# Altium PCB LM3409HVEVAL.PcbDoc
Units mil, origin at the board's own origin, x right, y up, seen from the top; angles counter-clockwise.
Board outline 6000 x 4000 mil, 2 copper layers (Top Layer, Bottom Layer); 38 components, 19 nets, 100 pads, 4 vias.
Unrouted connection lines stored in the file: 78.
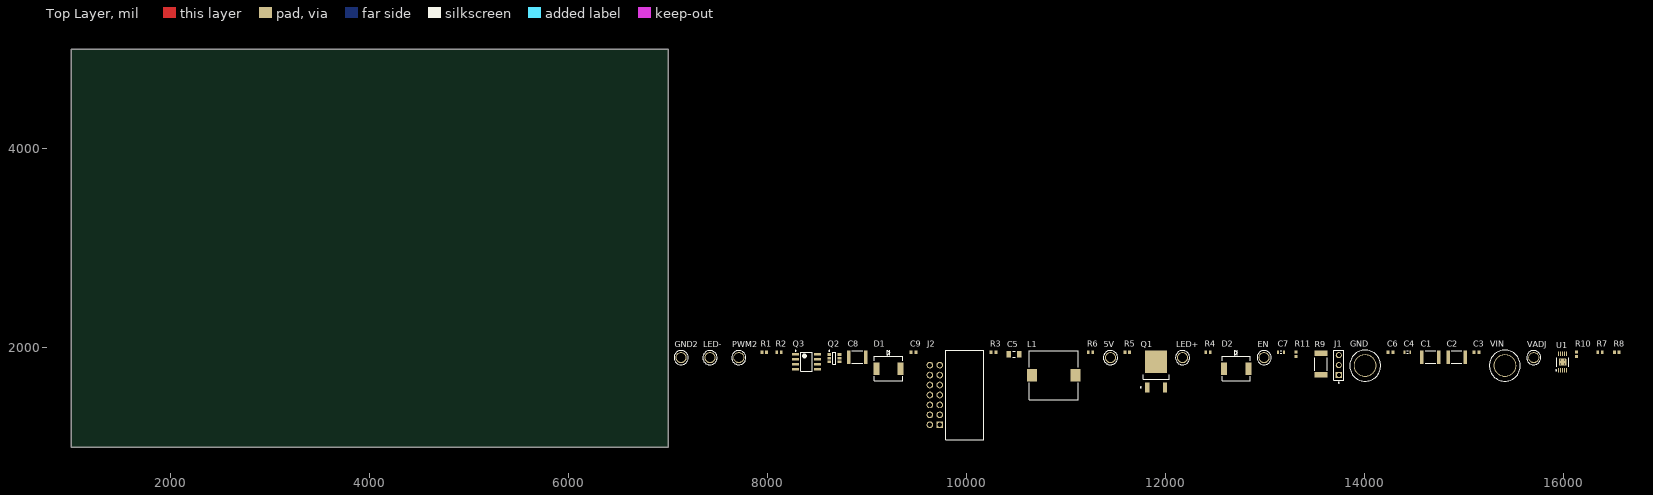
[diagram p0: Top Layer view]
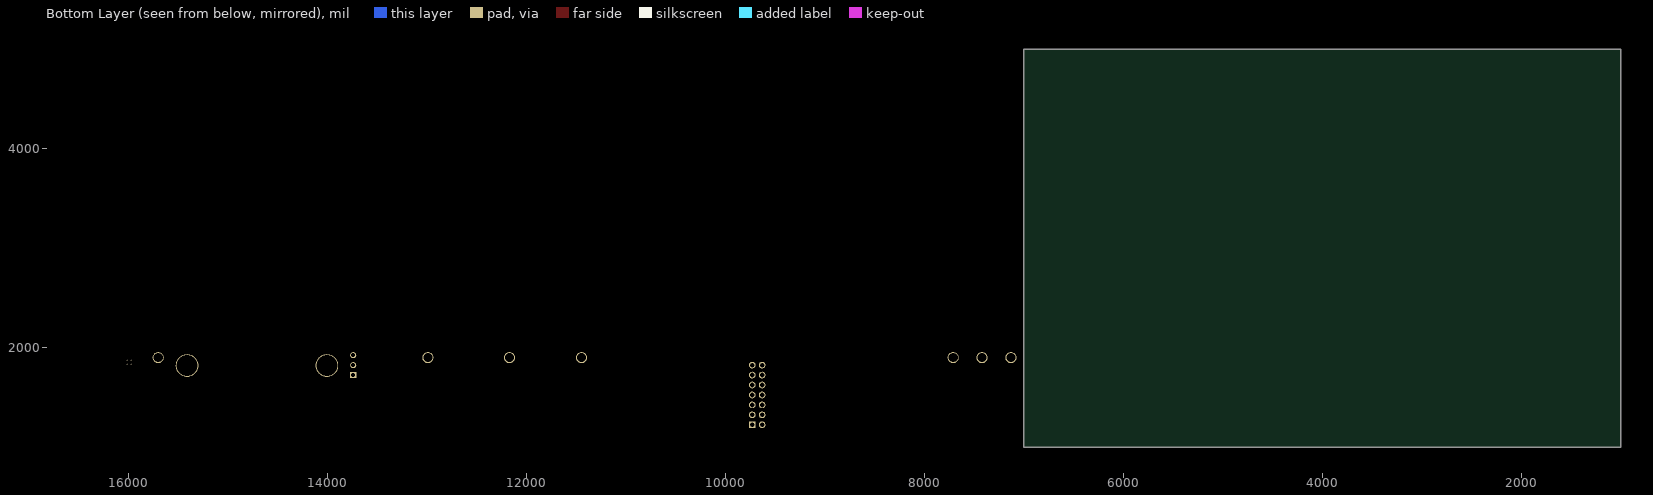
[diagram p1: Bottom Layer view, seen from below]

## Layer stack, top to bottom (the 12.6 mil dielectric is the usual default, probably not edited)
Top Solder: solder mask 0.4, Solder Resist, Dk 3.5
Top Layer: signal copper 1.4
Dielectric 1: dielectric 12.6, FR-4, Dk 4.8
Bottom Layer: signal copper 1.4
Bottom Solder: solder mask 0.4, Solder Resist, Dk 3.5

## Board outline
1000,1000 7000,1000 7000,5000 1000,5000

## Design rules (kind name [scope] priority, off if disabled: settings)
Clearance [All] p1: gap=10
PolygonConnect [All] p1: connectstyle=Relief reliefconductorwidth=10 reliefentries=4 polygonreliefangle="90 Angle" airgapwidth=10
RoomDefinition LM3409HVEVAL [InComponentClass('LM3409HVEVAL')] p1: confinementstyle=ConfineIn formatcopy=TRUE lockcomponents=FALSE outline 7045,1065 16620,1065 16620,2085 7045,2085
RoutingVias [All] p1: holewidth=28 width=50 viastyle="Through Hole" minholewidth=28 minwidth=50 maxholewidth=28 maxwidth=50
SolderMaskExpansion [All] p1: expansion=4
Width [All] p1: maxlimit=10 minlimit=10 preferedwidth=10
30 further rules are at their usual default settings.

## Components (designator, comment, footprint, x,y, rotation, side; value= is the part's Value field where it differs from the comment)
5V "1502-2" KSTN-1502-2 11445,1900 r0 top
C1 "2.2uF" CAPC4532X270X30LL40 14660,1905 r0 top
C2 "2.2uF" CAPC4532X270X30LL40 14925,1905 r0 top
C3 "0.1uF" CAPC1608X90X35LL10T15 15125,1955 r0 top
C4 "1.0uF" CAPC1608X90X20LL10 14430,1955 r0 top
C5 "0.1uF" CAPC3216X95X55LL15T25 10475,1935 r0 top
C6 "0.1uF" CAPC1608X90X35LL10T15 14260,1955 r0 top
C7 "470pF" CAPC1608X90X20LL10 13160,1955 r0 top
C8 "2.2uF" CAPC4532X270X30LL40 8900,1905 r0 top
C9 "2200pF" CAPC1608X90X35LL10T15 9465,1955 r0 top
D1 "SS3H10-E3/57T" VSH-DO-214AB-2_V 9215,1790 r0 top
D2 "SS3H10-E3/57T" VSH-DO-214AB-2_V 12710,1790 r0 top
EN "1502-2" KSTN-1502-2 12990,1900 r0 top
GND "575-8" KSTN-575-8 14005,1820 r0 top
GND2 "1502-2" KSTN-1502-2 7130,1900 r0 top
J1 "22-28-4033" MOLX-22-28-4033_V 13740,1825 r90 top
J2 "TSSH-107-01-S-D-RA" SMTC-TSSH-107-01-S-D-RA 9730,1225 r90 top
L1 "33uH" TDK-SLF12575-H_V 10875,1725 r0 top
LED+ "1502-2" KSTN-1502-2 12170,1900 r0 top
LED- "1502-2" KSTN-1502-2 7420,1900 r0 top
PWM2 "1502-2" KSTN-1502-2 7710,1900 r0 top
Q1 "ZXMP10A18KTC" DIOD-TO252-3_V 11905,1760 r90 top
Q2 "FDC6333C" FAIR-SOT23-6_V 8670,1895 r0 top
Q3 "FDS3672" FAIR-SO8_V 8390,1860 r0 top
R1 "1R" RESC1609X50X30LL10T20 7965,1955 r0 top
R2 "1R" RESC1609X50X30LL10T20 8115,1955 r0 top
R3 "10k" RESC1609X55X30LL10T20 10270,1955 r0 top
R4 "100R" RESC1609X50X30LL10T20 12425,1955 r0 top
R5 "0R" RESC1609X50X30LL10T20 11615,1955 r0 top
R6 "16k5" RESC1609X50X30LL10T20 11245,1955 r0 top
R7 "6k98" RESC1609X50X30LL10T20 16365,1955 r0 top
R8 "49R9" RESC1609X50X30LL10T20 16535,1955 r0 top
R9 "0R15" RESC6432X89X76LL25T25 13560,1835 r90 top
R10 "1k" RESC1609X50X30LL10T20 16130,1935 r90 top
R11 "16k5" RESC1609X50X30LL10T20 13310,1935 r90 top
U1 "LM3409HVMY/NOPB" DGQ0010A_L 15990,1855 r90 top
VADJ "1502-2" KSTN-1502-2 15700,1900 r0 top
VIN "575-8" KSTN-575-8 15410,1820 r0 top

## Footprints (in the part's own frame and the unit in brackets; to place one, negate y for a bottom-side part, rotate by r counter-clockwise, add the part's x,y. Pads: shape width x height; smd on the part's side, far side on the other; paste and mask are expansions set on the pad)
CAPC1608X90X20LL10 [mm]
  rect 0.45x0.85 smd: 1(-0.75,0) 2(0.75,0)
  silkscreen extent -0.15,-0.33 0.15,0.33, body extent -0.85,-0.45 0.85,0.45, height 0.9
CAPC1608X90X35LL10T15 [mm]
  rect 0.75x0.85 smd: 1(-0.625,0) 2(0.625,0)
  body extent -0.85,-0.45 0.85,0.45, height 0.9
CAPC3216X95X55LL15T25 [mm]
  rect 1.15x1.7 smd: 1(-1.3,0) 2(1.3,0)
  silkscreen extent -0.35,-0.75 0.35,0.75, body extent -1.68,-0.87 1.68,0.88, height 0.95
CAPC4532X270X30LL40 [mm]
  rect 0.85x3.4 smd: 1(-2.175,0) 2(2.175,0)
  silkscreen extent -1.35,-1.6 1.35,1.6, body extent -2.45,-1.75 2.45,1.75, height 2.7
DGQ0010A_L [mm] "TSOP, 10-Leads, Body 3.1x3.1mm, Pitch 0.5mm, Thermal Pad 1.9x1.73mm, IPC High Density"
  rrect40% 1.15x0.25 smd: 1(-2.125,1) 2(-2.125,0.5) 3(-2.125,0) 4(-2.125,-0.5) 5(-2.125,-1) 6(2.125,-1) 7(2.125,-0.5) 8(2.125,0) 9(2.125,0.5) 10(2.125,1)
  rrect6% 1.73x1.9 smd: 11(0,0)
  silkscreen extent -2.25,-1.55 1.15,1.8, body extent -2.45,-1.5 2.45,1.5, height 0.94
DIOD-TO252-3_V [mm]
  rect 2.6x1.06 smd: 1(-4.05,2.286) 2(-4.05,-2.286)
  rect 5.7x5.632 smd: 3(2.5,0)
  silkscreen extent -4.17,-3.35 -0.75,4.02, body extent -4.63,-3.35 5.28,3.35, height 2.39
FAIR-SO8_V [mm]
  rect 1.75x0.65 smd: 1(-2.8,1.905) 2(-2.8,0.635) 3(-2.8,-0.635) 4(-2.8,-1.905) 5(2.8,-1.905) 6(2.8,-0.635) 7(2.8,0.635) 8(2.8,1.905)
  silkscreen extent -2.92,-2.45 1.53,2.9, body extent -3,-2.5 3,2.5, height 1.75
FAIR-SOT23-6_V [mm]
  rect 1x0.7 smd: 1(-1.3,0.95) 2(-1.3,0) 3(-1.3,-0.95) 4(1.3,-0.95) 5(1.3,0) 6(1.3,0.95)
  silkscreen extent -1.42,-1.5 0.4,1.97, body extent -1.4,-1.45 1.4,1.45, height 1.45
KSTN-575-8 [mm]
  round 5.81 hole 5.31: 1(0,0)
  silkscreen extent -3.96,-3.96 3.96,3.96, body extent -3.96,-3.96 3.96,3.96, height 2.36
KSTN-1502-2 [mm]
  round 2.84 hole 2.34: 1(0,0)
  silkscreen extent -1.82,-1.82 1.82,1.82, body extent -1.59,-1.59 1.59,1.59, height 5.56
MOLX-22-28-4033_V [mm]
  rect 1.55x1.55 hole 1.02: 1(-2.54,0)
  round 1.55 hole 1.02: 2(0,0) 3(2.54,0)
  silkscreen extent -4.58,-1.24 3.81,1.24, body extent -3.81,-1.24 3.81,1.24, height 8.38
RESC1609X50X30LL10T20 [mm]
  rect 0.7x0.85 smd: 1(-0.575,0) 2(0.575,0)
  body extent -0.82,-0.48 0.82,0.48, height 0.5
RESC1609X55X30LL10T20 [mm]
  rect 0.75x0.85 smd: 1(-0.625,0) 2(0.625,0)
  body extent -0.85,-0.48 0.85,0.48, height 0.55
RESC6432X89X76LL25T25 [mm]
  rect 1.45x3.35 smd: 1(-2.75,0) 2(2.75,0)
  silkscreen extent -1.65,-1.58 1.65,1.58, body extent -3.3,-1.72 3.3,1.72, height 0.89
SMTC-TSSH-107-01-S-D-RA [mm]
  rect 1.7x1.7 hole 1.2: 1(0,0)
  round 1.7 hole 1.2: 2(0,2.54) 3(2.54,0) 4(2.54,2.54) 5(5.08,0) 6(5.08,2.54) 7(7.62,0) 8(7.62,2.54) 9(10.16,0) 10(10.16,2.54) 11(12.7,0) 12(12.7,2.54) 13(15.24,0) 14(15.24,2.54)
  silkscreen extent -3.81,-11.17 19.05,-1.52, body extent -3.81,-11.17 19.05,2.86, height 7.37
TDK-SLF12575-H_V [mm]
  rect 2.6x3.2 smd: 1(-5.55,0) 2(5.55,0)
  silkscreen extent -6.25,-6.25 6.25,6.25, body extent -6.25,-6.25 6.25,6.25, height 7.85
VSH-DO-214AB-2_V [mm]
  rect 1.52x3.2 smd: 1(-3.105,0) 2(3.105,0)
  silkscreen extent -3.6,-3.15 3.6,4.7, body extent -3.77,-3.11 3.77,3.11, height 2.62

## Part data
5V EN GND2 LED+ LED- PWM2 VADJ: library part CMP-1672-00001-3, "turret"
C1 C2 C8: library part CMP-1662-00004-2, "2.2µF X7R 10% 100V"
C3: library part CMP-1662-00005-2, "0.1µF X7R 10% 100V"
C4: library part CMP-1663-00002-2, "1.0µF X7R 10% 16V"
C5: library part CMP-1662-00007-2, "0.1µF X7R 10% 50V"
C6: library part CMP-1662-00003-2, "0.1µF X7R 10% 50V"
C7: library part CMP-1663-00001-2, "470pF X7R 10% 50V"
C9: library part CMP-1662-00006-2, "2200pF X7R 10% 50V"
D1 D2: library part CMP-1666-00013-2, "Schottky 100V 3A"
GND VIN: library part CMP-1672-00007-3, "banana jack"
J1: library part CMP-1676-00001-3, "3 pin header"
J2: library part CMP-1681-00003-3, "2x7 pin RA shrouded"
L1: library part CMP-1663-00003-2, "33 µH 20% 3.2A"
Q1: library part CMP-1668-00001-3, "PMOS 100V 3.8A"
Q2: library part CMP-1670-00004-2, "CMOS 30V 2A"
Q3: library part CMP-1670-00003-2, "NMOS 100V 7.5A"
R1 R2: library part CMP-1666-00006-2, "1O 1%"
R3: library part CMP-1666-00005-2, "10kO 1%"
R4: library part CMP-1666-00008-2, "100O 1%"
R5: library part CMP-1666-00007-2, "0O 1%"
R6 R11: library part CMP-1666-00002-2, "16.5kO 1%"
R7: library part CMP-1666-00001-2, "6.98kO 1%"
R8: library part CMP-1666-00004-2, "49.9kO 1%"
R9: library part CMP-1666-00009-2, "0.15O 1% 1W"
R10: library part CMP-1666-00003-2, "1kO 1%"
U1: library part CMP-0063-01397-3, "PFET Buck Controller for High Power LED Drives, 10-pin eMSOP, Pb-Free"

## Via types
v1: diameter 15.75, hole 7.87, Top Layer to Bottom Layer, 4 vias

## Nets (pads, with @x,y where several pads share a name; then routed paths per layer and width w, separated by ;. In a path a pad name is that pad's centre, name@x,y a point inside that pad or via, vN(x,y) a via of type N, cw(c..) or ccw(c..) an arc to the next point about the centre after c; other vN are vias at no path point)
GND: C1.2 C2.2 C3.2 C5.2 C6.1 C7.2 C8.2 D1.1 GND2.1 GND.1 J2.4 J2.5 J2.6 J2.9 J2.10 J2.11 LED-.1 Q2.5 Q3.1 Q3.2 Q3.3 R7.1 U1.5 U1.11
  other v1: 15970.32,1835.32 16009.69,1835.32 15970.32,1874.68 16009.69,1874.68
Net5V_1: 5V.1 C5.1 Q2.2 R3.2 R4.1
NetC1_1: C1.1 C2.1 C3.1 C4.1 J1.1 R8.2 R9.2 R11.2 U1.8 U1.10 VIN.1
NetC4_2: C4.2 U1.9
NetC6_2: C6.2 R10.2 U1.2
NetC7_1: C7.1 R6.2 R11.1 U1.4
NetC8_1: C8.1 J2.1 J2.2 J2.12 J2.13 J2.14 L1.2 LED+.1 Q3.5 Q3.6 Q3.7 Q3.8 R6.1
NetC9_1: C9.1 J1.3 R4.2
NetC9_2: C9.2 Q2.4 Q2.6 R1.1
NetD1_2: D1.2 L1.1 Q1.3
NetD2_1: D2.1 Q1.1 R5.2
NetD2_2: D2.2 R5.1 U1.6
NetEN_1: EN.1 J1.2 U1.3
NetPWM2_1: PWM2.1 R2.1 R3.1
NetQ1_2: Q1.2 R9.1 U1.7
NetQ2_1: Q2.1 Q2.3 R2.2
NetQ3_4: Q3.4 R1.2
NetR7_2: R7.2 R8.1 U1.1
NetR10_1: R10.1 VADJ.1
pads on no net: J2.3 J2.7 J2.8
